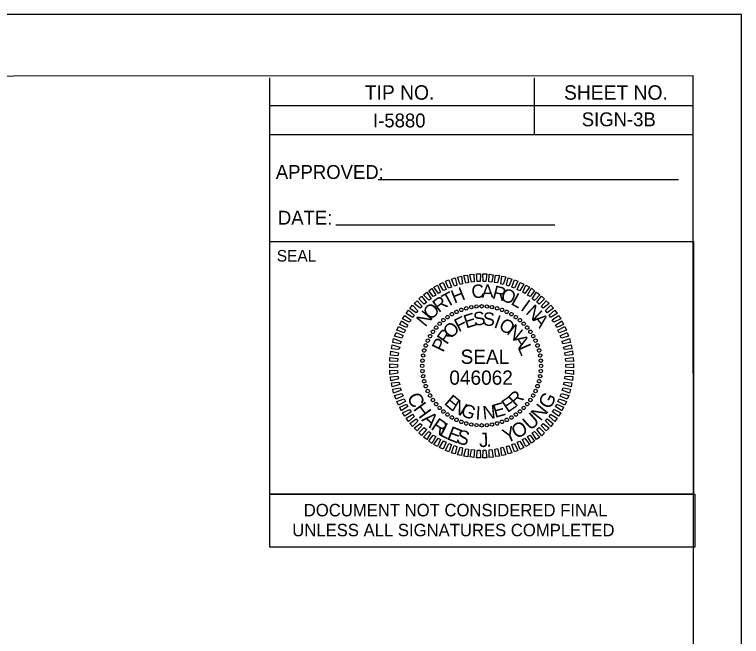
# Model space of a CAD drawing. Extents: x 1725232 to 1728895, y 538685 to 540544.
# Drawn here: x 1725504.7 to 1725568.8, y 539459.8 to 539514.6 of the extents above; entities that cross this region are included whole.
import ezdxf

# ---------------------------------------------------------------- set-up
doc = ezdxf.new("R2010")
doc.units = 0
for name, color, linetype in [('Default', 7, 'Continuous'), ('Old_Level_2', 7, 'Continuous'), ('Overhead Sheet Border', 7, 'Continuous'), ('Overhead Sheet Text', 7, 'Continuous'), ('Sheet Plot Border Outside CELL', 7, 'Continuous'), ('Sheet Sticker Exception Certification CELL', 7, 'Continuous')]:
    doc.layers.add(name, color=color, linetype=linetype)

msp = doc.modelspace()

# ---------------------------------------------------------------- linework, layer by layer
at = {"layer": 'Old_Level_2'}
for p, q in [((1725545.018, 539488.76), (1725545.018, 539488.76)), ((1725545.466, 539488.83), (1725545.466, 539488.83)), ((1725545.926, 539488.849), (1725545.926, 539488.849)), ((1725546.387, 539488.825), (1725546.387, 539488.825)), ((1725546.838, 539488.76), (1725546.838, 539488.76)), ((1725547.278, 539488.674), (1725547.278, 539488.674)), ((1725543.303, 539488.144), (1725543.303, 539488.144)), ((1725543.707, 539488.36), (1725543.707, 539488.36)), ((1725544.122, 539488.535), (1725544.122, 539488.535)), ((1725544.559, 539488.668), (1725544.559, 539488.668)), ((1725547.72, 539488.535), (1725547.72, 539488.535)), ((1725548.142, 539488.354), (1725548.142, 539488.354)), ((1725548.553, 539488.152), (1725548.553, 539488.152)), ((1725542.548, 539487.629), (1725542.548, 539487.629)), ((1725542.909, 539487.897), (1725542.909, 539487.897)), ((1725548.934, 539487.897), (1725548.934, 539487.897)), ((1725549.305, 539487.621), (1725549.305, 539487.621)), ((1725541.9, 539486.98), (1725541.9, 539486.98)), ((1725542.209, 539487.309), (1725542.209, 539487.309)), ((1725549.635, 539487.313), (1725549.635, 539487.313)), ((1725549.954, 539486.974), (1725549.954, 539486.974)), ((1725541.37, 539486.228), (1725541.37, 539486.228)), ((1725541.625, 539486.609), (1725541.625, 539486.609)), ((1725550.222, 539486.612), (1725550.222, 539486.612)), ((1725550.469, 539486.219), (1725550.469, 539486.219)), ((1725541.168, 539485.816), (1725541.168, 539485.816)), ((1725550.686, 539485.815), (1725550.686, 539485.815)), ((1725540.848, 539484.953), (1725540.848, 539484.953)), ((1725540.987, 539485.395), (1725540.987, 539485.395)), ((1725550.86, 539485.4), (1725550.86, 539485.4)), ((1725550.993, 539484.963), (1725550.993, 539484.963)), ((1725540.762, 539484.512), (1725540.762, 539484.512)), ((1725551.085, 539484.504), (1725551.085, 539484.504)), ((1725540.673, 539483.601), (1725540.673, 539483.601)), ((1725540.696, 539484.061), (1725540.696, 539484.061)), ((1725545.924, 539483.598), (1725545.924, 539483.598)), ((1725551.156, 539484.056), (1725551.156, 539484.056)), ((1725551.174, 539483.596), (1725551.174, 539483.596)), ((1725540.691, 539483.141), (1725540.691, 539483.141)), ((1725551.151, 539483.135), (1725551.151, 539483.135)), ((1725540.762, 539482.692), (1725540.762, 539482.692)), ((1725551.085, 539482.684), (1725551.085, 539482.684)), ((1725540.854, 539482.234), (1725540.854, 539482.234)), ((1725540.987, 539481.797), (1725540.987, 539481.797)), ((1725550.86, 539481.802), (1725550.86, 539481.802)), ((1725550.999, 539482.243), (1725550.999, 539482.243)), ((1725541.161, 539481.381), (1725541.161, 539481.381)), ((1725541.378, 539480.977), (1725541.378, 539480.977)), ((1725550.679, 539481.38), (1725550.679, 539481.38)), ((1725541.625, 539480.584), (1725541.625, 539480.584)), ((1725550.223, 539480.588), (1725550.223, 539480.588)), ((1725550.477, 539480.969), (1725550.477, 539480.969)), ((1725541.893, 539480.223), (1725541.893, 539480.223)), ((1725542.213, 539479.883), (1725542.213, 539479.883)), ((1725549.639, 539479.887), (1725549.639, 539479.887)), ((1725549.947, 539480.217), (1725549.947, 539480.217)), ((1725542.542, 539479.575), (1725542.542, 539479.575)), ((1725542.913, 539479.299), (1725542.913, 539479.299)), ((1725548.938, 539479.3), (1725548.938, 539479.3)), ((1725549.299, 539479.568), (1725549.299, 539479.568)), ((1725543.294, 539479.044), (1725543.294, 539479.044)), ((1725543.706, 539478.842), (1725543.706, 539478.842)), ((1725544.127, 539478.661), (1725544.127, 539478.661)), ((1725544.569, 539478.523), (1725544.569, 539478.523)), ((1725545.01, 539478.436), (1725545.01, 539478.436)), ((1725546.829, 539478.437), (1725546.829, 539478.437)), ((1725547.288, 539478.528), (1725547.288, 539478.528)), ((1725547.725, 539478.661), (1725547.725, 539478.661)), ((1725548.14, 539478.836), (1725548.14, 539478.836)), ((1725548.545, 539479.052), (1725548.545, 539479.052)), ((1725545.46, 539478.371), (1725545.46, 539478.371)), ((1725545.921, 539478.348), (1725545.921, 539478.348)), ((1725546.381, 539478.366), (1725546.381, 539478.366))]:
    msp.add_line(p, q, dxfattribs=at)
for points in [[(1725543.521, 539490.627), (1725543.269, 539491.25), (1725543.592, 539491.35), (1725543.739, 539490.704)], [(1725544.02, 539490.771), (1725543.789, 539491.426), (1725544.143, 539491.506), (1725544.239, 539490.828)], [(1725544.52, 539490.895), (1725544.341, 539491.561), (1725544.686, 539491.599), (1725544.771, 539490.931)], [(1725545.021, 539490.967), (1725544.894, 539491.634), (1725545.249, 539491.682), (1725545.271, 539491.002)], [(1725545.543, 539491.028), (1725545.479, 539491.707), (1725545.824, 539491.702), (1725545.794, 539491.022)], [(1725546.045, 539491.026), (1725546.033, 539491.706), (1725546.378, 539491.702), (1725546.296, 539491.02)], [(1725546.568, 539491.004), (1725546.598, 539491.685), (1725546.944, 539491.628), (1725546.82, 539490.967)], [(1725547.072, 539490.929), (1725547.154, 539491.6), (1725547.5, 539491.554), (1725547.323, 539490.902)], [(1725547.607, 539490.824), (1725547.7, 539491.505), (1725548.057, 539491.428), (1725547.827, 539490.775)], [(1725548.111, 539490.696), (1725548.257, 539491.347), (1725548.583, 539491.248), (1725548.332, 539490.627)], [(1725542.11, 539489.964), (1725541.713, 539490.522), (1725542.034, 539490.695), (1725542.306, 539490.093)], [(1725542.555, 539490.223), (1725542.21, 539490.803), (1725542.532, 539490.955), (1725542.784, 539490.321)], [(1725543.011, 539490.45), (1725542.729, 539491.052), (1725543.04, 539491.183), (1725543.272, 539490.518)], [(1725548.585, 539490.516), (1725548.814, 539491.179), (1725549.109, 539491.059), (1725548.827, 539490.447)], [(1725549.059, 539490.326), (1725549.31, 539490.947), (1725549.636, 539490.807), (1725549.291, 539490.215)], [(1725549.544, 539490.094), (1725549.816, 539490.695), (1725550.133, 539490.522), (1725549.745, 539489.972)], [(1725541.263, 539489.374), (1725540.804, 539489.868), (1725541.083, 539490.093), (1725541.459, 539489.513)], [(1725541.654, 539489.695), (1725541.258, 539490.221), (1725541.527, 539490.425), (1725541.882, 539489.824)], [(1725549.957, 539489.819), (1725550.312, 539490.431), (1725550.588, 539490.217), (1725550.189, 539489.697)], [(1725550.391, 539489.512), (1725550.768, 539490.094), (1725551.044, 539489.869), (1725550.592, 539489.37)], [(1725540.511, 539488.671), (1725539.971, 539489.09), (1725540.228, 539489.335), (1725540.676, 539488.841)], [(1725540.85, 539489.043), (1725540.382, 539489.495), (1725540.628, 539489.75), (1725541.046, 539489.192)], [(1725550.794, 539489.195), (1725551.213, 539489.746), (1725551.469, 539489.5), (1725550.995, 539489.042)], [(1725551.177, 539488.836), (1725551.618, 539489.335), (1725551.873, 539489.089), (1725551.337, 539488.671)], [(1725540.152, 539488.267), (1725539.601, 539488.665), (1725539.827, 539488.941), (1725540.295, 539488.458)], [(1725551.549, 539488.466), (1725552.022, 539488.945), (1725552.247, 539488.666), (1725551.699, 539488.259)], [(1725539.539, 539487.44), (1725538.948, 539487.744), (1725539.152, 539488.04), (1725539.703, 539487.631)], [(1725539.846, 539487.864), (1725539.275, 539488.21), (1725539.468, 539488.516), (1725539.978, 539488.065)], [(1725551.87, 539488.063), (1725552.375, 539488.512), (1725552.579, 539488.212), (1725551.999, 539487.867)], [(1725552.15, 539487.64), (1725552.697, 539488.047), (1725552.901, 539487.736), (1725552.3, 539487.433)], [(1725539.296, 539486.986), (1725538.695, 539487.237), (1725538.847, 539487.564), (1725539.418, 539487.187)], [(1725552.429, 539487.184), (1725553.009, 539487.56), (1725553.15, 539487.239), (1725552.558, 539486.988)], [(1725539.095, 539486.502), (1725538.443, 539486.731), (1725538.594, 539487.058), (1725539.196, 539486.734)], [(1725552.646, 539486.738), (1725553.258, 539487.063), (1725553.4, 539486.73), (1725552.755, 539486.51)], [(1725538.894, 539486.038), (1725538.243, 539486.215), (1725538.373, 539486.541), (1725539.005, 539486.26)], [(1725552.843, 539486.25), (1725553.476, 539486.533), (1725553.597, 539486.211), (1725552.952, 539486.032)], [(1725538.746, 539485.533), (1725538.095, 539485.658), (1725538.163, 539486.004), (1725538.826, 539485.754)], [(1725553.019, 539485.751), (1725553.684, 539486.003), (1725553.753, 539485.659), (1725553.096, 539485.533)], [(1725538.545, 539484.494), (1725537.874, 539484.545), (1725537.91, 539484.902), (1725538.593, 539484.746)], [(1725538.619, 539485.029), (1725537.969, 539485.101), (1725538.036, 539485.458), (1725538.699, 539485.25)], [(1725553.153, 539485.251), (1725553.809, 539485.462), (1725553.878, 539485.107), (1725553.22, 539485.033)], [(1725553.256, 539484.751), (1725553.933, 539484.909), (1725553.971, 539484.554), (1725553.303, 539484.501)], [(1725538.501, 539483.992), (1725537.821, 539484.001), (1725537.836, 539484.346), (1725538.518, 539484.243)], [(1725553.328, 539484.25), (1725554.006, 539484.346), (1725554.033, 539483.991), (1725553.353, 539484)], [(1725538.5, 539483.469), (1725537.821, 539483.425), (1725537.814, 539483.781), (1725538.495, 539483.72)], [(1725553.347, 539483.728), (1725554.026, 539483.771), (1725554.033, 539483.415), (1725553.352, 539483.477)], [(1725538.519, 539482.946), (1725537.841, 539482.85), (1725537.814, 539483.206), (1725538.494, 539483.197)], [(1725553.346, 539483.205), (1725554.026, 539483.196), (1725554.011, 539482.85), (1725553.33, 539482.953)], [(1725538.591, 539482.445), (1725537.914, 539482.287), (1725537.876, 539482.642), (1725538.545, 539482.695)], [(1725553.303, 539482.702), (1725553.973, 539482.651), (1725553.937, 539482.295), (1725553.255, 539482.45)], [(1725538.694, 539481.945), (1725538.038, 539481.735), (1725537.97, 539482.089), (1725538.627, 539482.163)], [(1725538.828, 539481.445), (1725538.163, 539481.193), (1725538.094, 539481.537), (1725538.751, 539481.664)], [(1725553.101, 539481.663), (1725553.752, 539481.538), (1725553.685, 539481.192), (1725553.021, 539481.442)], [(1725553.228, 539482.167), (1725553.878, 539482.095), (1725553.811, 539481.738), (1725553.148, 539481.946)], [(1725539.004, 539480.946), (1725538.371, 539480.663), (1725538.25, 539480.985), (1725538.896, 539481.164)], [(1725552.953, 539481.158), (1725553.605, 539480.981), (1725553.474, 539480.655), (1725552.842, 539480.937)], [(1725539.201, 539480.458), (1725538.589, 539480.134), (1725538.448, 539480.466), (1725539.092, 539480.686)], [(1725552.752, 539480.695), (1725553.404, 539480.465), (1725553.253, 539480.139), (1725552.651, 539480.463)], [(1725539.418, 539480.012), (1725538.839, 539479.636), (1725538.697, 539479.958), (1725539.289, 539480.209)], [(1725539.698, 539479.557), (1725539.15, 539479.15), (1725538.946, 539479.46), (1725539.548, 539479.763)], [(1725552.308, 539479.756), (1725552.899, 539479.453), (1725552.695, 539479.156), (1725552.144, 539479.565)], [(1725552.551, 539480.21), (1725553.152, 539479.959), (1725553.001, 539479.632), (1725552.429, 539480.009)], [(1725539.977, 539479.133), (1725539.472, 539478.685), (1725539.268, 539478.985), (1725539.848, 539479.329)], [(1725552.002, 539479.332), (1725552.572, 539478.987), (1725552.379, 539478.68), (1725551.869, 539479.131)], [(1725540.298, 539478.731), (1725539.825, 539478.252), (1725539.601, 539478.53), (1725540.148, 539478.937)], [(1725540.67, 539478.361), (1725540.229, 539477.861), (1725539.974, 539478.108), (1725540.511, 539478.525)], [(1725551.336, 539478.526), (1725551.877, 539478.106), (1725551.619, 539477.861), (1725551.171, 539478.356)], [(1725551.695, 539478.929), (1725552.246, 539478.531), (1725552.02, 539478.255), (1725551.552, 539478.739)], [(1725541.053, 539478.001), (1725540.634, 539477.45), (1725540.379, 539477.697), (1725540.852, 539478.155)], [(1725541.456, 539477.684), (1725541.079, 539477.102), (1725540.803, 539477.327), (1725541.255, 539477.827)], [(1725550.585, 539477.822), (1725551.043, 539477.328), (1725550.765, 539477.104), (1725550.388, 539477.683)], [(1725550.997, 539478.154), (1725551.465, 539477.702), (1725551.219, 539477.446), (1725550.801, 539478.004)], [(1725541.89, 539477.378), (1725541.535, 539476.765), (1725541.259, 539476.98), (1725541.658, 539477.499)], [(1725542.303, 539477.103), (1725542.031, 539476.502), (1725541.714, 539476.674), (1725542.102, 539477.225)], [(1725549.737, 539477.232), (1725550.134, 539476.674), (1725549.813, 539476.501), (1725549.541, 539477.103)], [(1725550.193, 539477.502), (1725550.589, 539476.975), (1725550.321, 539476.772), (1725549.965, 539477.372)], [(1725542.788, 539476.87), (1725542.538, 539476.249), (1725542.211, 539476.39), (1725542.556, 539476.981)], [(1725543.262, 539476.68), (1725543.033, 539476.017), (1725542.738, 539476.137), (1725543.02, 539476.749)], [(1725543.736, 539476.5), (1725543.59, 539475.849), (1725543.264, 539475.948), (1725543.515, 539476.569)], [(1725548.326, 539476.57), (1725548.578, 539475.947), (1725548.255, 539475.847), (1725548.108, 539476.493)], [(1725548.836, 539476.746), (1725549.118, 539476.144), (1725548.807, 539476.013), (1725548.575, 539476.679)], [(1725549.292, 539476.974), (1725549.637, 539476.394), (1725549.315, 539476.242), (1725549.064, 539476.875)], [(1725544.24, 539476.373), (1725544.148, 539475.691), (1725543.791, 539475.769), (1725544.02, 539476.421)], [(1725544.776, 539476.267), (1725544.693, 539475.596), (1725544.347, 539475.643), (1725544.524, 539476.294)], [(1725545.279, 539476.192), (1725545.249, 539475.512), (1725544.903, 539475.569), (1725545.027, 539476.23)], [(1725545.802, 539476.17), (1725545.814, 539475.49), (1725545.469, 539475.495), (1725545.551, 539476.176)], [(1725546.304, 539476.168), (1725546.368, 539475.49), (1725546.023, 539475.494), (1725546.053, 539476.174)], [(1725546.826, 539476.23), (1725546.953, 539475.563), (1725546.598, 539475.514), (1725546.576, 539476.194)], [(1725547.327, 539476.301), (1725547.506, 539475.635), (1725547.161, 539475.598), (1725547.077, 539476.265)], [(1725547.827, 539476.425), (1725548.058, 539475.77), (1725547.704, 539475.691), (1725547.608, 539476.369)]]:
    msp.add_lwpolyline(points, close=True, dxfattribs=at)
for centre, major_axis in [((1725544.129, 539488.527), (-0.052, 0.142)), ((1725544.566, 539488.665), (-0.039, 0.145)), ((1725545.013, 539488.764), (-0.026, 0.148)), ((1725545.466, 539488.824), (-0.013, 0.15)), ((1725545.924, 539488.844), (0, 0.151)), ((1725546.381, 539488.824), (0.013, 0.15)), ((1725546.834, 539488.764), (0.026, 0.148)), ((1725547.281, 539488.665), (0.039, 0.145)), ((1725547.718, 539488.527), (0.052, 0.142)), ((1725542.915, 539487.895), (-0.086, 0.123)), ((1725543.301, 539488.141), (-0.075, 0.13)), ((1725543.707, 539488.352), (-0.064, 0.136)), ((1725548.14, 539488.352), (0.064, 0.136)), ((1725548.546, 539488.141), (0.075, 0.13)), ((1725548.932, 539487.895), (0.086, 0.123)), ((1725542.214, 539487.307), (-0.106, 0.106)), ((1725542.552, 539487.617), (-0.097, 0.115)), ((1725549.295, 539487.617), (0.097, 0.115)), ((1725549.633, 539487.307), (0.106, 0.106)), ((1725541.627, 539486.607), (-0.123, 0.086)), ((1725541.905, 539486.97), (-0.115, 0.097)), ((1725549.942, 539486.97), (0.115, 0.097)), ((1725550.22, 539486.607), (0.123, 0.086)), ((1725541.381, 539486.221), (-0.13, 0.075)), ((1725550.466, 539486.221), (0.13, 0.075)), ((1725540.994, 539485.392), (-0.142, 0.052)), ((1725541.169, 539485.815), (-0.136, 0.064)), ((1725550.678, 539485.815), (0.136, 0.064)), ((1725550.853, 539485.392), (0.142, 0.052)), ((1725540.857, 539484.956), (-0.145, 0.039)), ((1725550.99, 539484.956), (0.145, 0.039)), ((1725540.698, 539484.055), (-0.15, 0.013)), ((1725540.758, 539484.509), (-0.148, 0.026)), ((1725551.089, 539484.509), (0.148, 0.026)), ((1725551.149, 539484.055), (0.15, 0.013)), ((1725540.678, 539483.598), (-0.151, 0)), ((1725551.169, 539483.598), (0.151, 0)), ((1725540.698, 539483.141), (-0.15, -0.013)), ((1725551.149, 539483.141), (0.15, -0.013)), ((1725540.758, 539482.687), (-0.148, -0.026)), ((1725540.857, 539482.241), (-0.145, -0.039)), ((1725550.99, 539482.241), (0.145, -0.039)), ((1725551.089, 539482.687), (0.148, -0.026)), ((1725540.994, 539481.804), (-0.142, -0.052)), ((1725550.853, 539481.804), (0.142, -0.052)), ((1725541.169, 539481.381), (-0.136, -0.064)), ((1725541.381, 539480.975), (-0.13, -0.075)), ((1725550.466, 539480.975), (0.13, -0.075)), ((1725550.678, 539481.381), (0.136, -0.064)), ((1725541.627, 539480.589), (-0.123, -0.086)), ((1725541.905, 539480.226), (-0.115, -0.097)), ((1725549.942, 539480.226), (0.115, -0.097)), ((1725550.22, 539480.589), (0.123, -0.086)), ((1725542.214, 539479.889), (-0.106, -0.106)), ((1725542.552, 539479.58), (-0.097, -0.115)), ((1725549.295, 539479.58), (0.097, -0.115)), ((1725549.633, 539479.889), (0.106, -0.106)), ((1725542.915, 539479.301), (-0.086, -0.123)), ((1725543.301, 539479.055), (-0.075, -0.13)), ((1725548.546, 539479.055), (0.075, -0.13)), ((1725548.932, 539479.301), (0.086, -0.123)), ((1725543.707, 539478.844), (-0.064, -0.136)), ((1725544.129, 539478.669), (-0.052, -0.142)), ((1725544.566, 539478.531), (-0.039, -0.145)), ((1725545.013, 539478.432), (-0.026, -0.148)), ((1725545.466, 539478.373), (-0.013, -0.15)), ((1725545.924, 539478.353), (0, -0.151)), ((1725546.381, 539478.373), (0.013, -0.15)), ((1725546.834, 539478.432), (0.026, -0.148)), ((1725547.281, 539478.531), (0.039, -0.145)), ((1725547.718, 539478.669), (0.052, -0.142)), ((1725548.14, 539478.844), (0.064, -0.136))]:
    msp.add_ellipse(centre, major_axis=major_axis, ratio=0.999708, dxfattribs=at)
at = {"layer": 'Overhead Sheet Border'}
for p, q in [((1725527.254, 539503.996), (1725527.254, 539508.981)), ((1725550.585, 539503.994), (1725550.585, 539508.982)), ((1725527.254, 539506.541), (1725550.585, 539506.539)), ((1725550.585, 539506.539), (1725564.621, 539506.538)), ((1725527.254, 539503.996), (1725564.62, 539503.993)), ((1725527.254, 539494.568), (1725527.254, 539503.996))]:
    msp.add_line(p, q, dxfattribs=at)
for points in [[(1725564.585, 539509.159), (1725264.833, 539508.997), (1725264.945, 539299.171), (1725564.697, 539299.332)], [(1725527.254, 539494.568), (1725564.62, 539494.568), (1725564.62, 539472.306), (1725527.254, 539472.306)]]:
    msp.add_lwpolyline(points, close=True, dxfattribs=at)
at = {"layer": 'Overhead Sheet Text'}
for p, q in [((1725536.783, 539500.015), (1725563.284, 539500.015)), ((1725533.05, 539496.037), (1725552.39, 539496.037))]:
    msp.add_line(p, q, dxfattribs=at)
at = {"layer": 'Sheet Plot Border Outside CELL'}
msp.add_lwpolyline([(1725568.838, 539514.551), (1725232.256, 539514.551), (1725232.256, 539295.37), (1725568.838, 539295.37)], close=True, dxfattribs=at)
at = {"layer": 'Sheet Sticker Exception Certification CELL'}
for p, q in [((1725550.585, 539503.994), (1725550.585, 539508.982)), ((1725564.621, 539508.981), (1725564.621, 539508.981)), ((1725564.621, 539508.981), (1725564.621, 539508.981)), ((1725564.621, 539508.981), (1725564.621, 539508.981)), ((1725564.621, 539508.981), (1725564.621, 539508.981)), ((1725564.621, 539508.981), (1725564.621, 539508.981)), ((1725564.621, 539508.981), (1725564.621, 539508.981)), ((1725564.621, 539508.981), (1725564.621, 539508.981)), ((1725564.621, 539508.981), (1725564.621, 539508.981))]:
    msp.add_line(p, q, dxfattribs=at)
msp.add_lwpolyline([(1725527.254, 539472.306), (1725564.712, 539472.306), (1725564.712, 539467.61), (1725527.254, 539467.61)], close=True, dxfattribs=at)

# ---------------------------------------------------------------- texts
at = {"layer": 'Default'}
for s, rotation, p in [('C', 297.19982, (1725539.3, 539480.852)), ('G', 61.79975, (1725551.946, 539479.699)), ('H', 306.64359, (1725539.84, 539479.802)), ('N', 51.22881, (1725551.129, 539478.66)), ('A', 316.48339, (1725540.577, 539478.818)), ('U', 41.43471, (1725550.214, 539477.847)), ('R', 325.19604, (1725541.363, 539478.063)), ('L', 332.56827, (1725542.11, 539477.523)), ('O', 30.04125, (1725548.994, 539477.113)), ('E', 338.75242, (1725542.787, 539477.147)), ('S', 345.75909, (1725543.597, 539476.813)), ('Y', 22.24252, (1725548.086, 539476.757)), ('J', 3.03206, (1725545.715, 539476.427)), ('.', 8.21395, (1725546.364, 539476.437))]:
    msp.add_text(s, height=1.254, rotation=rotation, dxfattribs=at).set_placement(p)
at = {"layer": 'Old_Level_2'}
for s, height, rotation, p in [('C', 1.179, 7.21984, (1725545.099, 539489.514)), ('A', 1.179, 0.02029, (1725545.924, 539489.591)), ('R', 1.179, 345.62106, (1725546.803, 539489.565)), ('T', 1.179, 28.81974, (1725542.843, 539488.711)), ('H', 1.179, 21.61945, (1725543.517, 539489.068)), ('O', 1.179, 338.42113, (1725547.506, 539489.42)), ('L', 1.179, 331.22084, (1725548.433, 539489.049)), ('R', 1.179, 36.02047, (1725542.14, 539488.239)), ('I', 1.179, 324.02011, (1725549.288, 539488.562)), ('O', 1.179, 43.22171, (1725541.43, 539487.578)), ('N', 1.179, 316.81888, (1725549.744, 539488.246)), ('N', 1.179, 50.42347, (1725540.959, 539486.963)), ('E', 1.179, 17.61103, (1725544.559, 539486.879)), ('S', 1.179, 8.25558, (1725545.277, 539487.112)), ('S', 1.179, 358.90037, (1725546.029, 539487.135)), ('I', 1.179, 340.18957, (1725546.931, 539487.005)), ('A', 1.179, 309.61712, (1725550.371, 539487.64)), ('O', 1.179, 45.68121, (1725543.216, 539485.925)), ('F', 1.179, 26.967, (1725543.895, 539486.554)), ('O', 1.179, 330.83345, (1725547.352, 539486.865)), ('R', 1.179, 55.03962, (1725542.859, 539485.406)), ('N', 1.179, 321.47658, (1725548.06, 539486.459)), ('A', 1.179, 302.76023, (1725548.665, 539485.926)), ('P', 1.179, 64.39886, (1725542.536, 539484.731)), ('L', 1.179, 293.40082, (1725549.085, 539485.212)), ('SEAL', 1.2545, 359.99997, (1725544.069, 539483.775)), ('046062', 1.2549, 359.99997, (1725543.074, 539481.934)), ('E', 1.179, 319.27686, (1725542.551, 539480.266)), ('R', 1.179, 43.48138, (1725548.937, 539479.938)), ('N', 1.179, 328.63392, (1725543.188, 539479.712)), ('E', 1.179, 15.41173, (1725547.102, 539479.006)), ('E', 1.179, 34.12406, (1725548.203, 539479.433)), ('G', 1.179, 337.99021, (1725543.991, 539479.255)), ('I', 1.179, 356.70117, (1725545.368, 539478.882)), ('N', 1.179, 6.05636, (1725546.069, 539478.863))]:
    msp.add_text(s, height=height, rotation=rotation, dxfattribs=at).set_placement(p)
at = {"layer": 'Overhead Sheet Text'}
for s, height, p in [('TIP NO.', 1.2705, (1725535.62, 539507.05)), ('SHEET NO.', 1.2705, (1725553.187, 539507.048)), ('I-5880', 1.2209, (1725536.345, 539504.608)), ('SIGN-3B', 1.2209, (1725554.751, 539504.709)), ('APPROVED:', 1.2209, (1725527.771, 539500.068)), ('DATE:', 1.2209, (1725527.954, 539496.043)), ('SEAL', 1.018, (1725527.858, 539492.788))]:
    msp.add_text(s, height=height, rotation=359.99494, dxfattribs=at).set_placement(p)
at = {"layer": 'Sheet Sticker Exception Certification CELL'}
for s, p in [('DOCUMENT NOT CONSIDERED FINAL', (1725530.235, 539470.337)), ('UNLESS ALL SIGNATURES COMPLETED', (1725529.222, 539468.579))]:
    msp.add_text(s, height=1.099, dxfattribs=at).set_placement(p)

doc.saveas('drawing.dxf')
